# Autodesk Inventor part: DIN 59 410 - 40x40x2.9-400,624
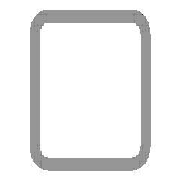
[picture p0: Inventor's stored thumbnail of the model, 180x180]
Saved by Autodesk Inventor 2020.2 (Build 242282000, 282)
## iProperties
Manager: www.cadconsulting.pl
Company: Fabian Stasiak CAD Consulting
_CCFamilyMember: 10
_CCFamilyDisplayName: DIN 59410 (Kwadrat) - Rurki stalowe o przekroju kwadratowym formowane na gorąco
_FrameMemberDoc: Frame Member File
_Version: 15.0.0
_GetPNFromCC: 1
Created: 2015-01
Part Number: DIN 59 410 - 40x40x2.9-400,624
Material: Stal, miękka
Description: Rurki stalowe o przekroju kwadratowym formowane na gorąco
Document SubType Name: Modellieren
Standard: DIN
Designer: F.Stasiak
Standards Organization: DIN
Language: pl-PL
Size Designation: 40x40x2.9
Categories: <MemberInstance><Categories><Category DisplayName="Kształtowniki konstrukcyjne" InternalName="089c4875-fa83-4c05-b084-43b9cc11f5ed" Mnemonic="GRDR"><CategoryPar
Stock Number: 40x40x2.9
Density: 7.85 g/cm^3
Appearance: Częściowo polerowana
Mass: 1157 g
Surface Area: 1028.03 cm^2
Volume: 147.388 cm^3
Catalog Web Link: www.expertbooks.pl
IsCustomPart: 1
G_W: 40,000 mm
G_H: 40,000 mm
+92630330-9BC0-4D05-8E6E-273B2CEB70B2+CUTDETAIL1: Wytnij
+1180CE4D-FA0B-432E-AE6E-11B8E74EED98+CUTDETAIL2: Wytnij
G_L: 400,624 mm
Author: F.Stasiak
Subject: Zbiór ćwiczeń. Autodesk Inventor 2020. Kurs Professional
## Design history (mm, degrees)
node "Płaszczyzna początkowa"
node "Płaszczyzna końcowa"
sketch "Szkic"
  geometry: L1 (-14.2, 20)-(14.2, 20); L2 (20, 14.2)-(20, -14.2); L3 (14.2, -20)-(-14.2, -20); L4 (-20, -14.2)-(-20, 14.2); L5 (-29.682, 0)-(29.682, 0) reference; L6 (0, -29.682)-(0, 29.682) reference; L7 (-14.2, 17.1)-(14.2, 17.1); L8 (17.1, 14.2)-(17.1, -14.2); L9 (14.2, -17.1)-(-14.2, -17.1); L10 (-17.1, -14.2)-(-17.1, 14.2); A1 r 5.8 centre (-14.2, 14.2) between (-14.2, 20) and (-20, 14.2); A2 r 5.8 centre (14.2, 14.2) between (20, 14.2) and (14.2, 20); A3 r 5.8 centre (14.2, -14.2) between (14.2, -20) and (20, -14.2); A4 r 5.8 centre (-14.2, -14.2) between (-20, -14.2) and (-14.2, -20); A5 r 2.9 centre (-14.2, 14.2) between (-14.2, 17.1) and (-17.1, 14.2); A6 r 2.9 centre (14.2, 14.2) between (17.1, 14.2) and (14.2, 17.1); A7 r 2.9 centre (14.2, -14.2) between (14.2, -17.1) and (17.1, -14.2); A8 r 2.9 centre (-14.2, -14.2) between (-17.1, -14.2) and (-14.2, -17.1); 3 further points
  constraints: 16 end point, 16 point on circle, 8 centre point, 8 tangent, 6 point on line, 4 parallel, 3 equal radius, 3 perpendicular, 1 horizontal, 7 other
  dimensions: "b" = 40 distance of point (-20, 20) point (20, 20); "msp_r" = 5.8 radius of A1 (= 2 x ParT); "d8" = 20 distance between parallel lines of L4 L6 (= d9); "d9" = 20 distance between parallel lines of L3 L5 (= 0.5 x b); "d10" = 2.9 distance between parallel lines of L3 L9 (= ParT)
extrude "Bryła" new body sketch "Szkic" taper "d4" = 0 deg; stored distance "NLG" = 10
node "Driven Length"
  sketch "Sketch2"
    geometry: L1 (0, 0)-(10, 0) reference
    constraints: 2 end point, 1 horizontal
  workplane "Work Plane3"
  sketch "Sketch3"
    geometry: L1 (-2, 15.355)-(12, 15.355) reference; L2 (-2, 415.98)-(12, 415.98) reference
    dimensions: "d14" = 400.62446 distance between parallel lines of L1 L2 (derived)
node "Płaszczyzna konstrukcyjna4"
feature "Podział1"
node "Płaszczyzna konstrukcyjna5"
feature "Podział2"
body "Solid1"
other parameters: "ParT" = 2.9, "G_OFFSET_START" = -15.35534 [user parameter; used in 1 equation term], "G_OFFSET_END" = -8.28427 [user parameter; used in 1 equation term], "d11" = 15.35534 (= -G_OFFSET_START), "d12" = 415.9798 (= G_OFFSET_END + B_L), "G_L" = 400.62446 (= d14) [user parameter], "B_L" = 424.26407 [user parameter; used in 1 equation term], "d13" = 90 deg
